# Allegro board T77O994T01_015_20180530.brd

Outline 210 x 96.2 mm; copper layers: TOP, G02, T03, G04, T05, P06, P07, T08, G09, T10, G11, BOTTOM. Coordinates in mm from the lower left corner of the outline.
Outline path: 0,95.2 0,12.7 arc(0.29,11.99) 1,11.7 14.7,11.7 14.7,3.2 15.2,2.7 25.4,2.7 25.9,3.2 25.9,10.3 arc(26.85,11.25) 27.8,10.3 27.8,3.2 28.3,2.7 98.5,2.7 99,3.2 99,10.75 arc(99.28,11.42) 99.95,11.7 121.55,11.7 arc(122.22,11.42) 122.5,10.75 122.5,0 209,0 arc(209.71,0.29) 210,1 210,95.2 arc(209.71,95.91) 209,96.2 1,96.2 arc(0.29,95.91) 0,95.2

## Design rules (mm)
net group BDX_CLKIN_SATA: nets BDX_CLKIN_SATA_N BDX_CLKIN_SATA_P
net group BUS-CPU_I2C2-1: nets LAN_MDC0_I2C_CLK_1V05 LAN_MDIO0_I2C_DATA_1V05
net group BUS-CPU_I2C2-2: nets LAN_MDC0_I2C_CLK_3V3 LAN_MDIO0_I2C_DATA_3V3
net group BUS-DDR4_TEST: nets PD_TEST0 PD_TEST1
net group BUS-DDR4_VREF: nets VP1P2_DDR4_AB_VREFCA VP1P2_DDR4_VREF
net group CLK_100M_PCIE0_SLOT: nets CLK_100M_PCIE0_SLOT_N CLK_100M_PCIE0_SLOT_P
net group CLK_100M_XDP_PE: nets CLK_100M_XDP_PE_N CLK_100M_XDP_PE_P
net group CPU_USB_P0: nets USB2_PCH_P0_DN USB2_PCH_P0_DP
net group DIFFPAIR0: nets USB2_PCH_P3_DN USB2_PCH_P3_DP
net group DIFFPAIR1: nets USB2_P2_DN USB2_P2_DP
net group G2_PCIE_RX0: nets G2_PCIE_RX0_N G2_PCIE_RX0_P
net group G2_PCIE_RX1: nets G2_PCIE_RX1_N G2_PCIE_RX1_P
net group G2_PCIE_TX0_AC_N: nets G2_PCIE_TX0_AC_N G2_PCIE_TX0_N
net group G2_PCIE_TX0_AC_P: nets G2_PCIE_TX0_AC_P G2_PCIE_TX0_P
net group G2_PCIE_TX1_AC_N: nets G2_PCIE_TX1_AC_N G2_PCIE_TX1_N
net group G2_PCIE_TX1_AC_P: nets G2_PCIE_TX1_AC_P G2_PCIE_TX1_P
net group G3_PCIE_RX0: nets G3_PCIE_RX0_N G3_PCIE_RX0_P
net group G3_PCIE_RX1: nets G3_PCIE_RX1_N G3_PCIE_RX1_P
net group G3_PCIE_RX2: nets G3_PCIE_RX2_N G3_PCIE_RX2_P
net group G3_PCIE_RX3: nets G3_PCIE_RX3_N G3_PCIE_RX3_P
net group G3_PCIE_TX0_AC_N: nets G3_PCIE_TX0_AC_N G3_PCIE_TX0_N
net group G3_PCIE_TX0_AC_P: nets G3_PCIE_TX0_AC_P G3_PCIE_TX0_P
net group G3_PCIE_TX1_AC_N: nets G3_PCIE_TX1_AC_N G3_PCIE_TX1_N
net group G3_PCIE_TX1_AC_P: nets G3_PCIE_TX1_AC_P G3_PCIE_TX1_P
net group G3_PCIE_TX2_AC_N: nets G3_PCIE_TX2_AC_N G3_PCIE_TX2_N
net group G3_PCIE_TX2_AC_P: nets G3_PCIE_TX2_AC_P G3_PCIE_TX2_P
net group G3_PCIE_TX3_AC_N: nets G3_PCIE_TX3_AC_N G3_PCIE_TX3_N
net group G3_PCIE_TX3_AC_P: nets G3_PCIE_TX3_AC_P G3_PCIE_TX3_P
net group P_CPU_CCS1: nets P_CPU_CCSN1_10 P_CPU_CCSP1_10
net group P_DDR4_VS: nets P_DDR4_CGFB_10 P_DDR4_CVFB_10
net group PD_CLKIN_CPY: nets PD_CLKIN_CPY_N PD_CLKIN_CPY_P
net group PD_CLKIN_DMI: nets PD_CLKIN_DMI_N PD_CLKIN_DMI_P
net group PD_CLKIN_DOT96: nets PD_CLKIN_DOT96_N PD_CLKIN_DOT96_P
net group PD_CPU_TSTCLK: nets PD_CPU_TSTCLK_N PD_CPU_TSTCLK_P
net group SATA3_SSD_RX_N: nets SATA3_SSD_RX_N SATA_P2_RX_N
net group SATA3_SSD_RX_P: nets SATA3_SSD_RX_P SATA_P2_RX_P
net group SATA3_SSD_TX_N: nets SATA3_SSD_TX_N SATA_P2_TX_AC_N
net group SATA3_SSD_TX_P: nets SATA3_SSD_TX_P SATA_P2_TX_AC_P
net group SFPP0_KR_RX0_AC_N: nets SFPP0_KR_RX0_AC_N SFPP0_KR_RX0_N
net group SFPP0_KR_RX0_AC_P: nets SFPP0_KR_RX0_AC_P SFPP0_KR_RX0_P
net group SFPP0_KR_TX0: nets SFPP0_KR_TX0_N SFPP0_KR_TX0_P
net group SFPP1_KR_RX1_AC_N: nets SFPP1_KR_RX1_AC_N SFPP1_KR_RX1_N
net group SFPP1_KR_RX1_AC_P: nets SFPP1_KR_RX1_AC_P SFPP1_KR_RX1_P
net group SFPP1_KR_TX1: nets SFPP1_KR_TX1_N SFPP1_KR_TX1_P
net group USB2_PCH_P1_D: nets USB2_PCH_P1_DN USB2_PCH_P1_DP
net group USB2_PCH_P2_D: nets USB2_PCH_P2_DN USB2_PCH_P2_DP
net group VP1P05_SNS: nets VP1P05_GSNS VP1P05_VSNS
net group BUS-DDR4_A-ADDR/COMM: nets DDR4_A_A0 DDR4_A_A1 DDR4_A_A2 DDR4_A_A3 DDR4_A_A4 DDR4_A_A5 DDR4_A_A6 DDR4_A_A7 DDR4_A_A8 DDR4_A_A9 DDR4_A_A10 DDR4_A_A11 DDR4_A_A12 DDR4_A_A13 DDR4_A_A14 DDR4_A_A15 DDR4_A_A16 DDR4_A_ACT_L DDR4_A_BA0 DDR4_A_BA1 DDR4_A_BG0 DDR4_A_BG1 DDR4_A_PAR
net group BUS-DDR4_A-ALERT: nets DDR4_A_ALERT_L
net group BUS-DDR4_A-CONTROL: nets DDR4_A_CKE0 DDR4_A_CKE1 DDR4_A_CS0_L DDR4_A_CS1_L DDR4_A_ODT0 DDR4_A_ODT1
net group BUS-DDR4_A-DATA_0: nets DDR4_A_DQ0 DDR4_A_DQ1 DDR4_A_DQ2 DDR4_A_DQ3 DDR4_A_DQ4 DDR4_A_DQ5 DDR4_A_DQ6 DDR4_A_DQ7 DDR4_A_DQS0_N DDR4_A_DQS0_P
net group BUS-DDR4_A-DATA_1: nets DDR4_A_DQ8 DDR4_A_DQ9 DDR4_A_DQ10 DDR4_A_DQ11 DDR4_A_DQ12 DDR4_A_DQ13 DDR4_A_DQ14 DDR4_A_DQ15 DDR4_A_DQS1_N DDR4_A_DQS1_P
net group BUS-DDR4_A-DATA_2: nets DDR4_A_DQ16 DDR4_A_DQ17 DDR4_A_DQ18 DDR4_A_DQ19 DDR4_A_DQ20 DDR4_A_DQ21 DDR4_A_DQ22 DDR4_A_DQ23 DDR4_A_DQS2_N DDR4_A_DQS2_P
net group BUS-DDR4_A-DATA_3: nets DDR4_A_DQ24 DDR4_A_DQ25 DDR4_A_DQ26 DDR4_A_DQ27 DDR4_A_DQ28 DDR4_A_DQ29 DDR4_A_DQ30 DDR4_A_DQ31 DDR4_A_DQS3_N DDR4_A_DQS3_P
net group BUS-DDR4_A-DATA_4: nets DDR4_A_DQ32 DDR4_A_DQ33 DDR4_A_DQ34 DDR4_A_DQ35 DDR4_A_DQ36 DDR4_A_DQ37 DDR4_A_DQ38 DDR4_A_DQ39 DDR4_A_DQS4_N DDR4_A_DQS4_P
net group BUS-DDR4_A-DATA_5: nets DDR4_A_DQ40 DDR4_A_DQ41 DDR4_A_DQ42 DDR4_A_DQ43 DDR4_A_DQ44 DDR4_A_DQ45 DDR4_A_DQ46 DDR4_A_DQ47 DDR4_A_DQS5_N DDR4_A_DQS5_P
net group BUS-DDR4_A-DATA_6: nets DDR4_A_DQ48 DDR4_A_DQ49 DDR4_A_DQ50 DDR4_A_DQ51 DDR4_A_DQ52 DDR4_A_DQ53 DDR4_A_DQ54 DDR4_A_DQ55 DDR4_A_DQS6_N DDR4_A_DQS6_P
net group BUS-DDR4_A-DATA_7: nets DDR4_A_DQ56 DDR4_A_DQ57 DDR4_A_DQ58 DDR4_A_DQ59 DDR4_A_DQ60 DDR4_A_DQ61 DDR4_A_DQ62 DDR4_A_DQ63 DDR4_A_DQS7_N DDR4_A_DQS7_P
net group BUS-DDR4_A-DATA_8: nets DDR4_A_DQS8_N DDR4_A_DQS8_P DDR4_A_ECC0 DDR4_A_ECC1 DDR4_A_ECC2 DDR4_A_ECC3 DDR4_A_ECC4 DDR4_A_ECC5 DDR4_A_ECC6 DDR4_A_ECC7
net group BUS-DDR4_A_CLK: nets CLK_DDR4_A_CK0_N CLK_DDR4_A_CK0_P CLK_DDR4_A_CK2_N CLK_DDR4_A_CK2_P
net group BUS-DDR4_A_OTHER: nets DDR4_A_SA0 DDR4_A_SA1 DDR4_A_SA2
net group BUS-DDR4_B-ADDR/COMM: nets DDR4_B_A0 DDR4_B_A1 DDR4_B_A2 DDR4_B_A3 DDR4_B_A4 DDR4_B_A5 DDR4_B_A6 DDR4_B_A7 DDR4_B_A8 DDR4_B_A9 DDR4_B_A10 DDR4_B_A11 DDR4_B_A12 DDR4_B_A13 DDR4_B_A14 DDR4_B_A15 DDR4_B_A16 DDR4_B_ACT_L DDR4_B_BA0 DDR4_B_BA1 DDR4_B_BG0 DDR4_B_BG1 DDR4_B_PAR
net group BUS-DDR4_B-ALERT: nets DDR4_B_ALERT_L
net group BUS-DDR4_B-CONTROL: nets DDR4_B_CKE0 DDR4_B_CKE1 DDR4_B_CS0_L DDR4_B_CS1_L DDR4_B_ODT0 DDR4_B_ODT1
net group BUS-DDR4_B-DATA_0: nets DDR4_B_DQ0 DDR4_B_DQ1 DDR4_B_DQ2 DDR4_B_DQ3 DDR4_B_DQ4 DDR4_B_DQ5 DDR4_B_DQ6 DDR4_B_DQ7 DDR4_B_DQS0_N DDR4_B_DQS0_P
net group BUS-DDR4_B-DATA_1: nets DDR4_B_DQ8 DDR4_B_DQ9 DDR4_B_DQ10 DDR4_B_DQ11 DDR4_B_DQ12 DDR4_B_DQ13 DDR4_B_DQ14 DDR4_B_DQ15 DDR4_B_DQS1_N DDR4_B_DQS1_P
net group BUS-DDR4_B-DATA_2: nets DDR4_B_DQ16 DDR4_B_DQ17 DDR4_B_DQ18 DDR4_B_DQ19 DDR4_B_DQ20 DDR4_B_DQ21 DDR4_B_DQ22 DDR4_B_DQ23 DDR4_B_DQS2_N DDR4_B_DQS2_P
net group BUS-DDR4_B-DATA_3: nets DDR4_B_DQ24 DDR4_B_DQ25 DDR4_B_DQ26 DDR4_B_DQ27 DDR4_B_DQ28 DDR4_B_DQ29 DDR4_B_DQ30 DDR4_B_DQ31 DDR4_B_DQS3_N DDR4_B_DQS3_P
net group BUS-DDR4_B-DATA_4: nets DDR4_B_DQ32 DDR4_B_DQ33 DDR4_B_DQ34 DDR4_B_DQ35 DDR4_B_DQ36 DDR4_B_DQ37 DDR4_B_DQ38 DDR4_B_DQ39 DDR4_B_DQS4_N DDR4_B_DQS4_P
net group BUS-DDR4_B-DATA_5: nets DDR4_B_DQ40 DDR4_B_DQ41 DDR4_B_DQ42 DDR4_B_DQ43 DDR4_B_DQ44 DDR4_B_DQ45 DDR4_B_DQ46 DDR4_B_DQ47 DDR4_B_DQS5_N DDR4_B_DQS5_P
net group BUS-DDR4_B-DATA_6: nets DDR4_B_DQ48 DDR4_B_DQ49 DDR4_B_DQ50 DDR4_B_DQ51 DDR4_B_DQ52 DDR4_B_DQ53 DDR4_B_DQ54 DDR4_B_DQ55 DDR4_B_DQS6_N DDR4_B_DQS6_P
net group BUS-DDR4_B-DATA_7: nets DDR4_B_DQ56 DDR4_B_DQ57 DDR4_B_DQ58 DDR4_B_DQ59 DDR4_B_DQ60 DDR4_B_DQ61 DDR4_B_DQ62 DDR4_B_DQ63 DDR4_B_DQS7_N DDR4_B_DQS7_P
net group BUS-DDR4_B-DATA_8: nets DDR4_B_DQS8_N DDR4_B_DQS8_P DDR4_B_ECC0 DDR4_B_ECC1 DDR4_B_ECC2 DDR4_B_ECC3 DDR4_B_ECC4 DDR4_B_ECC5 DDR4_B_ECC6 DDR4_B_ECC7
net group BUS-DDR4_B_CLK: nets CLK_DDR4_B_CK0_N CLK_DDR4_B_CK0_P CLK_DDR4_B_CK2_N CLK_DDR4_B_CK2_P
net group BUS-DDR4_B_OTHER: nets DDR4_B_SA0 DDR4_B_SA1 DDR4_B_SA2
net group BUS-DDR4_RCOMP: nets DDR_RCOMP0 DDR_RCOMP1 DDR_RCOMP2
net group BUS-SPI-1: nets SPI_SSB_CS0_L
net group BUS-UART: nets CPU_UART0_TXD_1V05 CPU_UART0_TXD_3V3 CPU_UART1_TXD_1V05 CPU_UART1_TXD_3V3
net group BUS_LED: nets LED_CPLD_1 LED_CPLD_1_R LED_CPLD_2 LED_CPLD_2_R LED_CPLD_3 LED_CPLD_3_R LED_CPLD_4 LED_CPLD_4_R
net group CLK: nets CLK_25M_CPLD CLK_25M_CPLD_ST CLK_33M_BUF CLK_33M_BUF_ST CLK_33M_LPC CLK_33M_LPC_EDGE CLK_33M_LPC_EDGE_ST CLK_33M_LPC_HDR CLK_33M_LPC_HDR_ST CLK_33M_LPC_ST CLK_M2_SUSCLK CLK_M2_SUSCLK_ST
net group POWER: nets N50983122 N50983135 P_CPU_CCSN1+_10 P_CPU_CCSN2+_10 P_CPU_CCSP1+_10 P_CPU_CCSP2+_10 P_CPU_SKIP#_1_10 P_CPU_SKIP#_2_10 P_CPU_SKIP#_10 PWRGD_VP1P05_PCH PWRGD_VP2P5_DDR4_VPP VFLTP1P05_PCH VP0P6_DDR4_VTT_REFOUT VP1P3_FB VP1P3_SS VP1P5__PCH_FB VP1P05_BLEED VP1P05_PCH_SLEWRATE VP1P5_PCH_SS VP1P7_COMP VP1P7_COMP_RC VP1P7_FB VP1P7_RT VP1P7_SNS VP1P7_SS VP2P5 VP2P5_DDR4_VPP_FB VP2P5_DDR4_VPP_FB_IN VP2P5_DDR4_VPP_L_RC VP2P5_DDR4_VPP_SN VP2P5_DDR4_VPP_SS VP3P3_A_BLEED VP3P3_BAT VP3P3_BAT_SOURCE VP3P3_SF100 VP3P3_SPI VP3P3_VFB VP3P3_VREG5 VP3P3_VSENSE VP5P0_FB VP5P0_FB_IN VP5P0_L_RC VP5P0_SN VP5P0_SS
net group POWER_20MIL: nets P_CPU_CPWM1_10 P_CPU_CPWM1_DR1_10 P_CPU_CPWM2_10 P_CPU_CPWM2_DR2_10 P_CPU_DR1_BST_20 P_CPU_DR1_BST_RC_20 P_CPU_DR1_BSTR_20 P_CPU_DR2_BST_20 P_CPU_DR2_BST_RC_20 P_CPU_DR2_BSTR_20 P_CPU_SB1_20 P_CPU_SB2_20 P_DDR4_CPWM1_DR1_10 P_DDR4_DR1_BST_20 P_DDR4_DR1_BST_RC_20 P_DDR4_DR1_BSTR_20 P_DDR4_PWM1 P_DDR4_SB1_20 VP1P7_BOOT VP2P5_DDR4_VPP_BST VP2P5_DDR4_VPP_BST_RC VP3P3_BST VP3P3_BSTR VP3P3_SNUBBER VP5P0_BST VP5P0_BST_RC
net group SMB_I2C: nets DDR4_SCL_2V5 DDR4_SCL_2V5_ST DDR4_SDA_1V05 DDR4_SDA_1V05_ST LAN_I2C0_SCL_1V05_R LAN_I2C0_SDA_1V05_R LAN_I2C1_SCL_1V05_R LAN_I2C1_SDA_1V05_R SMB_SMLINK0_3V3SB_CLK SMB_SMLINK0_3V3SB_DAT SMB_SMLINK1_3V3SB_CLK SMB_SMLINK1_3V3SB_DAT
net group SPI: nets SPI_BUF_SSB_CLK SPI_BUF_SSB_CS0_L SPI_BUF_SSB_CS1_L SPI_BUF_SSB_MISO_ST SPI_BUF_SSB_MOSI SPI_MUX_SSB_CS0_L SPI_SSB_CLK SPI_SSB_CLK_ST
net group SVID: nets BDXDE_SVID_ALERT_L P_CPU_ALERT P_CPU_VCLK P_CPU_VDIO P_DDR4_ALERT P_DDR4_VCLK P_DDR4_VDIO SVID_CPU_ALERT_L SVID_CPU_DIO VP1P05_ALERT
net group UART: nets CPU_UART0_RXD_1V05 CPU_UART0_RXD_3V3 CPU_UART1_RXD_1V05 CPU_UART1_RXD_3V3
net group XTAL: nets BDXDE_RTCX1 BDXDE_RTCX2 KR_EPHY_REFCLK_IN KR_EPHY_REFCLK_OUT XTAL_PCH_25M_IN XTAL_PCH_25M_OUT

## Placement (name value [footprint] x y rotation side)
BAT1  BB3320E-1  [BA-D23_1X5_8-3S0]  204.45 42.53 90 top
C1  220nF  [C-0402S0]  49.38 12.59 180 top
C2  220nF  [C-0402S0]  53.26 12.72 180 top
C3  220nF  [C-0402S0]  57.38 12.46 180 top
C4  220nF  [C-0402S0]  61.44 12.46 180 top
C5  220nF  [C-0402S0]  50.52 12.59 180 top
C6  220nF  [C-0402S0]  54.33 12.72 180 top
C7  220nF  [C-0402S0]  58.4 12.49 180 top
C8  220nF  [C-0402S0]  62.46 12.46 180 top
C9  100nF  [C-0402S0]  78.38 12.51 180 top
C10  100nF  [C-0402S0]  74.4 12.31 180 top
C11  100nF  [C-0402S0]  79.4 12.51 180 top
C12  100nF  [C-0402S0]  75.41 12.31 180 top
C13  100nF  [C-0402S0]  103.86 52.98 270 top
C14  100nF  [C-0402S0]  103.94 48.53 270 top
C15  100nF  [C-0402S0]  103.86 52.03 270 top
C16  100nF  [C-0402S0]  103.94 49.47 270 top
C17  27pF  [C-0402S0]  104.42 55.24 180 top
C18  27pF  [C-0402S0]  104.42 57.14 0 top
C19  100nF  [C-0402S0]  82.57 66.56 90 top
C20  100nF  [C-0402S0]  84.6 66.56 90 top
C21  100nF  [C-0402S0]  72.23 70.14 270 bottom
C22  100nF  [C-0402S0]  42.82 63.1 270 bottom
C23  100nF  [C-0402S0]  83.9 25.18 0 bottom
C24  100nF  [C-0402S0]  72.23 70.14 90 top
C25  100nF  [C-0402S0]  80.1 67.42 180 top
C26  18pF  [C-0402S0]  121.79 21.22 90 top
C27  18pF  [C-0402S0]  124.08 21.22 270 top
C28  100nF  [C-0402S0]  46.23 19.96 180 bottom
C29  100nF  [C-0402S0]  87.1 71.52 90 top
C30  100nF  [C-0402S0]  140.22 90.57 0 top
C31  1uF  [C-0402S0]  123.08 52.83 180 bottom
C32  1uF  [C-0402S0]  181.32 89.82 180 top
C33  1uF  [C-0402S0]  198.63 13.1 0 top
C34  22uF  [C-1210B-H2_8]  90.04 20.84 0 bottom
C35  1uF  [C-0402S0]  197.61 3.95 0 bottom
C36  10pF  [C-0402S0]  111.65 23.62 90 top
C37  10pF  [C-0402S0]  113.31 23.62 270 top
C38  100nF  [C-0402B-U58O293T00]  126.45 35.07 90 bottom
C39  47uF  [C-0805-H1_35]  99.97 45.1 0 top
C40  1uF  [C-0402B-U58O293T00]  116.51 47.19 0 bottom
C41  100nF  [C-0402B-U58O293T00]  123.8 43.17 180 bottom
C42  100nF  [C-0402B-U58O293T00]  123.83 34.57 90 bottom
C43  100nF  [C-0402B-U58O293T00]  123.83 33.75 90 bottom
C44  100nF  [C-0402S0]  36.31 56.53 90 top
C45  1uF  [C-0402B-U58O293T00]  125.03 36.57 180 bottom
C46  1uF  [C-0402B-U58O293T00]  119.93 41.88 90 bottom
C47  1uF  [C-0402B-U58O293T00]  119.22 32.97 0 bottom
C48  1uF  [C-0402B-U58O293T00]  118.81 34.18 90 bottom
C49  1uF  [C-0402B-U58O293T00]  119.03 35.37 270 bottom
C50  1uF  [C-0402B-U58O293T00]  119.03 36.17 90 bottom
C51  100nF  [C-0402S0]  51.91 82.96 180 bottom
C52  100nF  [C-0402B-U58O293T00]  120.63 36.17 90 bottom
C53  10nF  [C-0402S0]  126.31 38.66 0 bottom
C54  1uF  [C-0402S0]  83.34 27.55 90 top
C55  1uF  [C-0402S0]  119.4 51.53 0 bottom
C56  47uF  [C-0603S0]  118.28 49.93 90 bottom
C57  1uF  [C-0402B-U58O293T00]  121.81 36.54 180 bottom
C58  1uF  [C-0402B-U58O293T00]  122.23 37.77 90 bottom
C59  1uF  [C-0402B-U58O293T00]  123.77 39.62 315 bottom
C60  1uF  [C-0402B-U58O293T00]  121.43 39.37 270 bottom
C61  1uF  [C-0402B-U58O293T00]  122.23 38.57 270 bottom
C62  1uF  [C-0402B-U58O293T00]  119.04 37.77 270 bottom
C63  1uF  [C-0402B-U58O293T00]  118.23 38.57 270 bottom
C64  100nF  [C-0402B-U58O293T00]  122.63 36.57 180 bottom
C65  10uF  [C-0603S0]  94.38 31.62 0 bottom
C66  22uF  [C-0603S0]  122.96 46.48 270 bottom
C67  22uF  [C-0603S0]  122.98 47.85 270 bottom
C68  22uF  [C-0603S0]  126.89 46.27 270 bottom
C69  22uF  [C-0603S0]  126.89 47.7 270 bottom
C70  22uF  [C-0603S0]  122.96 49.22 270 bottom
C71  22uF  [C-0603S0]  123 50.59 270 bottom
C72  22uF  [C-0603S0]  123.01 45.11 270 bottom
C73  22uF  [C-0603S0]  126.87 51.96 270 bottom
C74  22uF  [C-0603S0]  129.97 53.23 90 bottom
C75  1uF  [C-0402B-U58O293T00]  118.23 39.37 270 bottom
C76  1uF  [C-0402B-U58O293T00]  120.23 37.37 0 bottom
C77  1uF  [C-0402B-U58O293T00]  121.44 40.17 270 bottom
C78  1uF  [C-0402B-U58O293T00]  119.99 40.02 180 bottom
C79  1uF  [C-0402B-U58O293T00]  122.63 40.57 180 bottom
C80  1uF  [C-0402B-U58O293T00]  124.43 41.67 180 bottom
C81  1uF  [C-0402B-U58O293T00]  121.26 41.12 270 bottom
C82  22uF  [C-0603S0]  129.94 47.75 90 bottom
C83  22uF  [C-0603S0]  129.94 46.38 90 bottom
C84  22uF  [C-0603S0]  129.97 51.86 90 bottom
C85  22uF  [C-0603S0]  129.97 50.49 90 bottom
C86  22uF  [C-0603S0]  129.94 49.12 90 bottom
C87  22uF  [C-0603S0]  126.89 49.09 270 bottom
C88  22uF  [C-0603S0]  126.89 50.49 270 bottom
C89  47uF  [C-0603S0]  118.28 47.19 90 bottom
C90  47uF  [C-0603S0]  118.28 48.56 90 bottom
C91  2.2uF  [C-0402S0]  117.75 42.64 90 bottom
C92  47uF  [C-0805-H1_35]  89.41 41.04 90 bottom
C93  47uF  [C-0603S0]  112.01 50.69 0 bottom
C94  47uF  [C-0603S0]  120.62 51 0 bottom
C95  47uF  [C-0603S0]  118.11 43.84 90 bottom
C96  47uF  [C-0603S0]  118.11 45.21 90 bottom
C97  100uF  [C-1210]  88.9 51.83 180.1 top
C98  47uF  [C-0805-H1_35]  89.41 36.72 90 bottom
C99  22uF  [C-0603S0]  132.28 45.46 270 bottom
C100  47uF  [C-0805-H1_35]  132.79 51.43 180 bottom
C101  47uF  [C-0805-H1_35]  132.79 48.13 0 bottom
C102  10uF  [C-0402A]  186.79 6.06 180 bottom
C103  1uF  [C-0402S0]  72.47 27.42 270 bottom
C104  22uF  [C-1210B-H2_8]  191.26 39.77 0 bottom
C107  100nF  [C-0402S0]  188.34 8.65 90 bottom
C108  100nF  [C-0402S0]  191.26 4.84 180 bottom
C114  47uF  [C-0805-H1_35]  102 38.35 270 top
C116  1uF  [C-0402S0]  32.35 44.61 90 top
C117  1uF  [C-0402S0]  38.19 65.06 90 bottom
C118  1uF  [C-0402S0]  31.73 41.29 270 top
C119  1uF  [C-0402S0]  27.24 69.1 90 top
C120  100nF  [C-0402S0]  93.55 25.18 90 bottom
C121  1uF  [C-0402S0]  27.41 65.29 270 bottom
C122  1uF  [C-0402S0]  26.65 31 180 top
C123  1uF  [C-0402S0]  82.77 26.45 0 bottom
C124  1uF  [C-0402S0]  47.37 29.1 180 top
C125  1uF  [C-0402S0]  68.55 28.61 180 top
C126  1uF  [C-0402S0]  46.61 24.53 180 top
C127  100nF  [C-0402S0]  139.55 81.17 180 top
C128  100nF  [C-0402S0]  120.56 34.58 180 bottom
C129  1uF  [C-0402S0]  36.93 31.77 180 top
C130  1uF  [C-0402S0]  38.24 69.74 270 top
C131  1uF  [C-0402S0]  72.92 31.61 180 top
C132  100nF  [C-0402S0]  199.01 10.68 90 bottom
C133  100nF  [C-0402S0]  182.05 3.93 180 bottom
C134  100nF  [C-0402S0]  187.83 12.34 90 bottom
C135  100nF  [C-0402S0]  155.54 3.84 180 top
C136  100nF  [C-0402S0]  167.35 4.4 90 bottom
C137  10nF  [C-0402S0]  155.42 65.55 270 top
C138  10uF  [C-0603S0]  189.89 83.45 90 bottom
C139  10uF  [C-0603S0]  162.15 79.36 180 top
C140  10uF  [C-0603S0]  178.59 91.05 270 top
C141  10uF  [C-0603S0]  174.2 89.7 270 bottom
C144  10nF  [C-0402S0]  175.18 61.13 180 bottom
C145  10uF  [C-0603S0]  160.76 79.36 180 top
C146  10uF  [C-0603S0]  189.89 82.06 90 bottom
C147  10uF  [C-0603S0]  178.59 89.62 270 top
C148  10uF  [C-0603S0]  178.51 89.7 90 bottom
C151  1uF  [C-0402B-U58O293T00]  116.63 52.83 90 bottom
C152  100nF  [C-0402S0]  84.17 19.46 0 top
C153  100nF  [C-0402S0]  123.71 37.03 180 bottom
C154  100nF  [C-0402S0]  167.39 10.05 270 bottom
C155  1uF  [C-0402S0]  53.48 60.89 90 bottom
C156  100nF  [C-0402S0]  200.41 12.97 0 bottom
C157  100nF  [C-0402S0]  72.42 26.02 90 top
C158  1uF  [C-0402S0]  67.23 41.46 180 top
C159  100uF  [C-1210]  61.21 28.21 180 top
C160  22uF  [C-0603S0]  62.71 47.13 270 top
C161  22uF  [C-0603S0]  37.06 35.45 90 top
C162  220nF  [C-0402S0]  50.13 37.63 0 bottom
C163  220nF  [C-0402S0]  47.39 39.23 0 bottom
C164  220nF  [C-0402S0]  42.65 53.1 0 top
C165  220nF  [C-0402S0]  37.19 36.72 90 top
C166  220nF  [C-0402S0]  48.26 44.59 180 bottom
C167  220nF  [C-0402S0]  46.96 43.16 90 bottom
C168  220nF  [C-0402S0]  51.15 37.12 0 bottom
C169  220nF  [C-0402S0]  52.32 41.29 270 bottom
C170  220nF  [C-0402S0]  50.29 43.83 0 bottom
C171  10pF  [C-0402S0]  61.95 37.73 270 top
C172  10pF  [C-0402S0]  37.31 47.39 90 top
C173  10pF  [C-0402S0]  42.8 55.01 270 top
C174  10pF  [C-0402S0]  45.94 32.29 90 bottom
C175  10pF  [C-0402S0]  61.95 38.75 270 top
C176  1uF  [C-0402B-U58O293T00]  121.83 34.17 0 bottom
C177  10nF  [C-0402S0]  114.58 29.08 270 bottom
C178  1uF  [C-0402S0]  114.58 30.09 270 bottom
C179  1uF  [C-0402B-U58O293T00]  124.58 38.17 0 bottom
C180  1uF  [C-0402B-U58O293T00]  125.03 34.97 0 bottom
C181  1uF  [C-0402B-U58O293T00]  122.96 43.19 180 bottom
C182  1uF  [C-0402S0]  135.28 29.84 90 bottom
C183  1uF  [C-0402B-U58O293T00]  128.21 37.8 225 bottom
C185  47uF  [C-0805-H1_35]  53.13 67.58 180 bottom
C186  100uF  [C-TAN-S7_3X4_3]  71.77 90.06 90 bottom
C187  100nF  [C-0402S0]  19.62 61.5 270 top
C188  100nF  [C-0402S0]  5.85 69.74 90 bottom
C189  100nF  [C-0402S0]  19.62 65.42 270 top
C190  47uF  [C-0805-H1_35]  11.4 73.19 180 bottom
C191  47uF  [C-0805-H1_35]  5.97 65.42 0 bottom
C192  100nF  [C-0402S0]  19.62 64.4 270 top
C193  100nF  [C-0402S0]  19.62 62.37 270 top
C198  100nF  [C-0402S0]  53.72 87.39 90 top
C199  10nF  [C-0402S0]  151.51 59.45 90 top
C200  100nF  [C-0402S0]  70.74 72.91 270 top
C201  10nF  [C-0402S0]  69.52 74.36 90 bottom
C202  10nF  [C-0402S0]  69.52 75.38 90 bottom
C203  10nF  [C-0402S0]  69.52 76.39 90 bottom
C204  10nF  [C-0402S0]  69.52 77.41 90 bottom
C205  100nF  [C-0402S0]  92.3 72.25 0 top
C206  100nF  [C-0402S0]  52.8 82.96 180 bottom
C207  1uF  [C-0402S0]  53.69 82.96 180 bottom
C208  22uF  [C-0805]  38.15 77.54 180 top
C209  1uF  [C-0402S0]  70.5 37.61 180 top
C210  1uF  [C-0402S0]  62.23 43.32 90 top
C3812  1uF  [C-0402B-U58O293T00]  119.03 36.97 90 bottom
C3813  1uF  [C-0402B-U58O293T00]  114.83 37.71 90 bottom
CN1  ASAA821-EARB0-7H  [CN-EXPPCI-260C]  182.2 50.54 90 bottom
CN2  AS0A826-H2RB-7H  [CN-EXPPCI-260A-T77O759]  170.46 50.59 90 top
D1  LTST-C190KGKT  [LD-0603S0]  146.02 13.11 0 top
D2  BAT54C-7-F  [SOT-23BH1_11]  194.89 40.55 270 bottom
D3  LTST-C190KGKT  [LD-0603S0-H0_55]  58.9 56.28 0 top
D4  LTST-C190KGKT  [LD-0603S0-H0_55]  57.51 56.28 0 top
D5  LTST-C190KGKT  [LD-0603S0-H0_55]  55.6 56.28 0 top
D6  LTST-C190KGKT  [LD-0603S0-H0_55]  54.2 56.28 0 top
D7  BAT54C-7-F  [SOT-23BH1_11]  164.05 11.21 90 top
D8  BAT54C-7-F  [SOT-23BH1_11]  83.82 21.99 180 bottom
H1  11802936A  [NUT165R276-H5_7]  19.63 74.44 180 bottom
J1  HS5507F-R  [CN-S7X2-2HDS1]  43.56 19.7 270 top
J2  20438-04021  [CN-S10_16X5_1-4]  147.32 5.99 90 top
J3  20438-04021  [CN-S10_16X5_1-4]  201.29 6.62 90 top
J6  HS1104V-RN  [CN-S4X2-2_54HD]  175.28 6.87 270 top
J8  HS1105H-RN  [CN-S5X2-2_54AHDS0]  26.26 19.95 270 top
J9  AS0BC23-S67BM-LH  [CN-EXPPCI-75G]  61.28 74.44 180 bottom
J10  10061913-113  [CN-EXPPCI-164FPCS0]  56.85 9.07 90 bottom
J11  26-01-3115  [CN-D2X2-4_2RT]  9.5 32.53 90 top
J12  QT510301-22-7F  [CN-S30X2-0_5ASK]  8.69 69.61 180 top
L1  0.02ohm  [R-1210]  95.44 34.79 0 top
L2  8.2nH  [L-U58O293T00]  96.67 42.03 0 top
L3  8.2nH  [L-U58O293T00]  96.67 38.88 0 top
L7  8.2nH  [L-U58O293T00]  104.92 34.81 180 bottom
M1  Hole-3.4mm  [GMTH134R394KO472]  5 88.2 0 top
M2  Hole-3.4mm  [GMTH134R394KO472]  205 19.7 0 top
M3  Hole-3.4mm  [GMTH134R394KO472]  5 19.69 0 top
M4  Hole-3.4mm  [GMTH134R394KO472]  205 88.2 0 top
MHS1  SMT NUT PAD  [ICT295PAS0]  101.08 21.2 0 top
MHS2  Screw  [MPTH126R295]  101.08 71.2 0 top
MHS3  SMT NUT PAD  [ICT295PAS0]  151.08 71.2 0 top
MHS4  Screw  [MPTH126R295]  151.08 21.2 0 top
NOREF  -  [unnamed]  194.84 17.13 0 top
NOREF#2  -  [unnamed]  15.59 89.34 0 top
NOREF#3  -  [unnamed]  194.23 86.16 0 top
NOREF#4  -  [unnamed]  15.59 89.34 180 bottom
NOREF#5  -  [unnamed]  194.84 17.13 180 bottom
NOREF#6  -  [unnamed]  194.23 86.16 180 bottom
PC1  22uF  [C-1210]  4 53 0 top
PC2  100nF  [C-0603S0]  30.81 91.6 180 top
PC3  100nF  [C-0603S0]  8.95 53 0 top
PC4  100nF  [C-0603S0]  13.7 44.66 0 top
PC5  100nF  [C-0402S0]  15.71 49.79 270 bottom
PC6  100nF  [C-0603S0]  16 52.85 180 bottom
PC7  1uF  [C-0603S0]  17.4 52.85 180 bottom
PC8  22uF  [C-1210]  20.45 52.34 180 bottom
PC9  22uF  [C-1210]  24.26 52.34 180 bottom
PC10  22uF  [C-1210]  21.21 52.21 0 top
PC11  8.2nF  [C-0402S0]  7.83 42.71 270 top
PC12  680pF  [C-0603S0]  10.88 53.26 180 bottom
PC13  1uF  [C-0603S0]  7.57 48.04 90 bottom
PC14  1nF  [C-0402S0]  14.3 48.3 0 bottom
PC15  100nF  [C-0402S0]  44.96 85.61 180 top
PC16  22uF  [C-1210]  42.29 85.87 180 top
PC17  22uF  [C-1210]  38.61 85.87 180 top
PC18  10pF  [C-0402S0]  47.19 79.06 0 top
PC19  100nF  [C-0402S0]  47.07 90.84 270 top
PC20  1uF  [C-0402S0]  49.27 79.06 180 top
PC21  1nF  [C-0402S0]  51.13 90.71 180 bottom
PC22  22uF  [C-1210]  53.85 80.79 90 top
PC23  22uF  [C-1210]  53.85 84.6 90 top
PC24  22uF  [C-0805]  31.62 77.49 90 top
PC25  100nF  [C-0402S0]  47.58 69.25 90 top
PC26  22uF  [C-0805]  48.13 70.88 90 top
PC27  1uF  [C-0402S0]  42.34 65.6 90 top
PC28  100nF  [C-0402S0]  31.62 75.84 90 top
PC29  10nF  [C-0402S0]  42.34 64.63 90 top
PC30  560pF  [C-0402S0]  49.76 64.28 180 top
PC31  22uF  [C-0805]  31.62 81.55 90 top
PC32  100nF  [C-0402S0]  57.53 71.77 0 top
PC33  22uF  [C-0805]  59.05 71.77 0 top
PC34  1uF  [C-0402S0]  52.82 76.82 0 top
PC35  100nF  [C-0402S0]  57.53 74.82 180 top
PC36  10nF  [C-0402S0]  51.86 76.82 0 top
PC37  560pF  [C-0402S0]  52.39 69.53 90 top
PC38  22uF  [C-0805]  130.05 85.11 180 bottom
PC39  22uF  [C-0805]  127.89 85.11 180 bottom
PC40  22uF  [C-0805]  125.73 85.11 180 bottom
PC41  22uF  [C-0805]  125.73 88.66 0 bottom
PC44  22uF  [C-0805]  130.05 92.22 180 bottom
PC45  22uF  [C-0805]  127.89 92.22 180 bottom
PC46  22uF  [C-0805]  125.73 92.22 180 bottom
PC47  22uF  [C-0805]  130.05 88.66 0 bottom
PC48  22uF  [C-0805]  127.89 88.66 0 bottom
PC52  22uF  [C-0805]  61.21 71.77 0 top
PC67  22pF  [C-0402S0]  27.38 83.47 180 top
PC68  100nF  [C-0402S0]  24.65 87.42 180 top
PC69  22uF  [C-1210]  21.72 86.76 180 top
PC70  22uF  [C-0805]  59.05 75.33 180 top
PC71  100nF  [C-0402S0]  45.04 69.25 270 top
PC72  22uF  [C-0805]  44.58 70.88 270 top
PC75  22uF  [C-0805]  197.36 49.42 180.2 top
PC77  1uF  [C-0402S0]  192.38 89.62 0 top
PC78  22uF  [C-0805]  186.56 90.95 0 bottom
PC79  22uF  [C-0805]  189.87 92.6 180 top
PC80  1uF  [C-0402S0]  191.52 9.41 90 bottom
PC81  1nF  [C-0402S0]  185.39 88.93 90 top
PC82  100nF  [C-0402S0]  180.82 93.23 90 top
PC83  1uF  [C-0402S0]  188.21 91.08 0 bottom
PC84  22uF  [C-0805]  192.33 92.55 180 top
PC111  22uF  [C-0805]  31.62 79.52 90 top
PC112  10pF  [C-0402S0]  28.07 91.31 0 top
PC113  100pF  [C-0402S0]  24.72 83.47 0 top
PC114  3.3nF  [C-0402S0]  30.05 83.47 180 top
PC115  22nF  [C-0402S0]  28.83 82.06 270 top
PC137  100nF  [C-0603S0]  155.02 83.43 90 top
PC139  100nF  [C-0603S0]  150.74 90.29 0 top
PC140  680pF  [C-0603S0]  152.67 90.55 180 bottom
PC142  10uF  [C-1206]  74.3 48.53 0 top
PC144  22uF  [C-1210B-H2_8]  75.82 47.77 180 bottom
PC146  22uF  [C-0805]  89.41 38.88 90.1 bottom
PC147  22uF  [C-0805]  89.96 51.98 0 bottom
PC148  22uF  [C-0805]  84.45 36.34 90 top
PC151  100nF  [C-0603S0]  74.12 38.55 180 top
PC152  470uF  [C-S7_3X4_3-2]  93.98 62.25 359.8 top
PC162  1uF  [C-0603S0]  200.3 32.66 90 bottom
PC163  100nF  [C-0603S0]  89.26 45.35 0 top
PC165  100nF  [C-0402S0]  95.14 87.77 270 top
PC166  2.2uF  [C-0603S0]  200.36 67.35 270 top
PC167  1nF  [C-0402S0]  108.6 88.86 270 bottom
PC168  10nF  [C-0402S0]  81.15 79.65 270 top
PC170  22uF  [C-1210B-H2_8]  91.57 82.31 180 top
PC171  100nF  [C-0402S0]  94.5 92.85 0 top
PC172  22uF  [C-1210B-H2_8]  87.88 82.31 180 top
PC173  470uF  [C-S7_3X4_3-2]  127.1 81.04 270 top
PC174  100uF  [C-TAN-S7_3X4_3]  15.26 20.72 0 top
PC175  1nF  [C-0402S0]  95.14 85.99 90 top
PC176  2.2uF  [C-0603S0]  104.79 88.15 180 top
PC177  1nF  [C-0402S0]  108.47 79.64 90 bottom
PC178  10nF  [C-0402S0]  79.63 80.28 90 top
PC179  470uF  [C-S7_3X4_3-2]  127.1 91.46 270 top
PC180  1nF  [C-0402S0]  95.14 76.09 90 top
PC182  22uF  [C-1210B-H2_8]  87.63 91.58 0 top
PC183  100nF  [C-0402S0]  94.5 80.79 180 top
PC184  22uF  [C-1210B-H2_8]  91.19 91.58 0 top
PC185  470uF  [C-S7_3X4_3-2]  127.1 86.25 270 top
PC186  100nF  [C-0402S0]  95.14 77.87 270 top
PC187  1uF  [C-0402S0]  76.94 70.63 180 top
PC188  1uF  [C-0402S0]  74.11 74.77 90 top
PC189  470nF  [C-0402S0]  74.1 77.31 90 top
PC190  220pF  [C-0402S0]  73.64 79.64 180 top
PC191  10pF  [C-0402S0]  74.52 79.64 180 top
PC192  1nF  [C-0402S0]  83.8 76.47 0 top
PC193  4.7nF  [C-0402S0]  85.08 75.15 270 top
PC194  22uF  [C-0805]  124.59 77.99 180 bottom
PC195  22uF  [C-0805]  123.57 81.55 0 bottom
PC196  22uF  [C-0805]  123.57 92.22 180 bottom
PC199  22uF  [C-0805]  119.13 92.22 180 bottom
PC200  22uF  [C-0805]  121.28 92.22 180 bottom
PC201  22uF  [C-0805]  125.73 81.55 0 bottom
PC202  22uF  [C-0805]  128.52 75.2 270 top
PC203  22uF  [C-0805]  123.57 85.11 180 bottom
PC204  22uF  [C-0805]  123.57 88.66 0 bottom
PC205  22uF  [C-0805]  128.91 77.99 180 bottom
PC206  22uF  [C-0805]  126.75 77.99 180 bottom
PC208  22uF  [C-0805]  130.05 81.55 0 bottom
PC209  22uF  [C-0805]  127.89 81.55 0 bottom
PC211  22uF  [C-0805]  128.52 77.34 270 top
PC212  22uF  [C-0805]  131.7 76.72 90 bottom
PC213  2.2uF  [C-0603S0]  104.79 77.99 180 top
PC214  1nF  [C-0402S0]  205.06 64.68 0 top
PC215  10nF  [C-0402S0]  193.42 25.29 90 top
PC216  100uF  [C-TAN-S7_3X4_3]  71.77 91.07 270 top
PC217  1nF  [C-0402S0]  202.56 75.58 0 top
PC218  1uF  [C-0603S0]  97.71 51.83 180 top
PC219  1uF  [C-0603S0]  73.51 76.98 180 bottom
PC220  22uF  [C-0805]  154.92 43.58 180 top
PC222  22uF  [C-1210B-H2_8]  190.5 70.63 270 bottom
PC223  100nF  [C-0402S0]  193.8 71.52 0 bottom
PC224  22uF  [C-0805]  158.22 43.58 180 top
PC225  22uF  [C-0805]  161.42 43.58 180 top
PC226  22uF  [C-0805]  155.75 60.72 0 top
PC227  22uF  [C-0805]  153.42 60.72 0 top
PC228  22uF  [C-0805]  194.82 59.71 0 top
PC229  22uF  [C-0805]  195.07 49.42 180 top
PC230  22uF  [C-0805]  191.64 49.42 180 top
PC231  22uF  [C-1210B-H2_8]  190.5 74.31 270 bottom
PC232  470uF  [C-S7_3X4_3-2]  159.46 62.39 0 top
PC233  1uF  [C-0402S0]  195.43 34.05 0 top
PC234  1uF  [C-0402S0]  198.3 28.13 270 bottom
PC235  470nF  [C-0402S0]  198.37 27.19 270 bottom
PC236  330pF  [C-0402S0]  196.44 21.37 270 top
PC237  470uF  [C-S7_3X4_3-2]  196.19 49.85 0 bottom
PC238  33pF  [C-0402S0]  196.44 22.39 270 top
PC239  1nF  [C-0402S0]  190.22 25.8 90 top
PC240  4.7nF  [C-0402S0]  190.22 27.83 90 top
PC241  100nF  [C-0402S0]  200.23 75.2 0 bottom
PC242  470uF  [C-S7_3X4_3-2]  191.01 47.64 0 bottom
PC243  22uF  [C-0805]  190.3 89.93 270 top
PC244  22uF  [C-0805]  192.66 59.71 0 top
PC246  100uF  [C-TAN-S7_3X4_3]  193.27 90.57 90 bottom
PC247  22uF  [C-0805]  93.32 45.1 180 bottom
PC248  22uF  [C-0805]  87.46 66.08 270 bottom
PC249  22uF  [C-0805]  95.78 51.98 0 bottom
PC250  22uF  [C-0805]  91.89 51.98 0 bottom
PC252  22uF  [C-0805]  96.88 47.26 270 bottom
PC255  100uF  [C-1210]  90.3 45.1 180 bottom
PC256  470uF  [C-S7_3X4_3-2]  85.6 47.01 180 bottom
PC257  22uF  [C-1210]  163.19 90.69 0 top
PC258  100nF  [C-0603S0]  162.43 90.34 180 bottom
PC259  22uF  [C-1210]  145.99 90.29 0 top
PC262  1uF  [C-0805]  149.11 90.29 0 top
PC263  22uF  [C-1210]  167.13 90.69 0 top
PC264  1uF  [C-0603S0]  86.25 32.51 90 top
PC265  22uF  [C-0805]  95.25 30.5 180 top
PC266  22uF  [C-0805]  93.85 51.98 0 bottom
PC267  10nF  [C-0402S0]  86.64 31.24 90 top
PC270  1uF  [C-0603S0]  39.32 74.33 90 top
PC271  22uF  [C-0805]  49.91 67.45 180 bottom
PC272  22uF  [C-0805]  39.37 72.66 90 top
PC273  3.3nF  [C-0402S0]  97.36 84.36 270 top
PC274  3.3nF  [C-0402S0]  95.9 92.85 0 top
PC275  3.3nF  [C-0402S0]  194.82 71.52 0 bottom
PC284  470uF  [C-S7_3X4_3-2]  191.01 60.09 180 bottom
PC292  470uF  [C-S7_3X4_3-2]  89.41 56.79 270 bottom
PC293  470uF  [C-S7_3X4_3-2]  95.6 38.12 180 bottom
PC295  1uF  [C-0603S0]  15.78 44.35 180 top
PC296  1uF  [C-0603S0]  8.97 41.44 90 top
PC297  1uF  [C-0603S0]  47.45 75.76 90 top
PC298  1uF  [C-0603S0]  18.54 82.44 180 top
PC299  1uF  [C-0603S0]  39.85 35.09 180 bottom
PC300  1uF  [C-0603S0]  52.29 30.77 270 bottom
PC301  1uF  [C-0603S0]  62.58 34.58 0 bottom
PC302  1uF  [C-0603S0]  55.34 30.77 270 bottom
PC303  1uF  [C-0603S0]  58.51 30.77 270 bottom
PC304  1uF  [C-0603S0]  45.81 29.5 270 bottom
PC305  1uF  [C-0603S0]  41.16 61.61 180 top
PC306  1uF  [C-0603S0]  43.15 30.01 270 bottom
PC307  100nF  [C-0402S0]  27.91 47.02 180 top
PC309  1uF  [C-0805]  7.18 53 0 top
PC312  1nF  [C-0402S0]  156.11 85.58 0 bottom
PC313  100nF  [C-0402S0]  157.5 87.08 270 bottom
PC316  22nF  [C-0402S0]  150.7 84.49 0 bottom
PC318  1uF  [C-0603S0]  166.75 90.26 180 bottom
PC322  1uF  [C-0603S0]  148.9 88.94 180 bottom
PC323  470uF  [C-S7_3X4_3-2]  93.98 52.34 180 top
PC324  470uF  [C-S7_3X4_3-2]  89.41 62.12 270 bottom
PC325  22uF  [C-0805]  96.88 49.29 270 bottom
PC326  22pF  [C-0402S0]  61.82 39.01 180 bottom
PC327  100uF  [C-TAN-S7_3X4_3]  71.77 85.74 270 top
PC328  1nF  [C-0402S0]  76.58 58.94 180 top
PC329  470nF  [C-0402S0]  68.07 50.56 180 bottom
PC330  3.3nF  [C-0402S0]  76.07 48.15 0 top
PC331  100nF  [C-0402S0]  78.74 40.02 180.1 top
PC332  1nF  [C-0402S0]  68.96 57.42 180 bottom
PC333  100nF  [C-0402S0]  82.04 45.74 89.6 top
PC334  6.8nF  [C-0402S0]  65.42 53.95 0 top
PC335  330pF  [C-0402S0]  65.91 46.5 180.1 top
PC336  1nF  [C-0402S0]  82.42 48.02 180 bottom
PC338  33pF  [C-0402S0]  66.42 48.91 270.2 top
PC339  4.7nF  [C-0402S0]  69.98 57.42 180 bottom
PC340  2.2uF  [C-0603S0]  82.68 51.96 0 bottom
PC347  1uF  [C-0402S0]  72.14 50.82 270 bottom
PC348  1uF  [C-0402S0]  69.22 50.56 180 bottom
PC349  22uF  [C-0805]  90.04 62.5 0 top
PJ20  0ohm  [R-0603-TESTS1]  72.11 78.88 0 top
PJ21  0ohm  [R-0603-TESTS1]  194.06 36.85 180 bottom
PJ22  0ohm  [R-0603-TESTS1]  66.29 55.52 270 bottom
PL1  2.2uH  [L-S5_49X5_18-2]  15.43 49.45 90 top
PL2  2.2uH  [L-S4_45X4_06-2AS0]  52.28 90.84 270 top
PL8  330nH 20% 20A 0.0035ohm  [L-S6_86X6_47-2A]  82.65 57.06 270 top
PL9  680nH  [L-S4_45X4_06-2AS0]  82.93 40.66 270 top
PL10  220nH  [L-S8_3X8_1-2]  111.9 89.55 270 top
PL11  330nH  [L-S6_86X6_47-2A]  80.92 88.79 270 top
PL12  330nH  [L-S6_86X6_47-2A]  195.95 79.79 270 bottom
PL13  220nH  [L-S8_3X8_1-2]  111.9 80.41 270 top
PL14  220nH  [L-S8_3X8_1-2]  201.26 59.98 0 bottom
PL15  2.2uH  [L-S5_49X5_18-2]  157.47 87.5 90 top
PL16  3.3uH 20% 5A 0.038ohm  [L-S5_49X5_18-2A]  33.61 86.01 180 top
PNTC2  100Kohm  [R-0402S0]  117.3 92.97 0 top
PNTC3  100Kohm  [R-0402S0]  111.08 74.97 270 top
PNTC4  100Kohm  [R-0402S0]  85.83 76.47 180 top
PNTC5  100Kohm  [R-0402S0]  190.22 24.78 270 top
PNTC6  100Kohm  [R-0402S0]  206.71 59.34 0 bottom
PNTC7  100Kohm  [R-0402S0]  68.07 57.42 180.8 top
PNTC8  100Kohm  [R-0402S0]  81.79 61.36 90 top
PR1  20Kohm  [R-0402S0]  8.97 40.17 90 top
PR2  20Kohm  [R-0402S0]  38.58 34.83 180 bottom
PR7  0.01ohm  [R-0805]  5.71 47.77 180 top
PR8  0.01ohm  [R-0805]  3.68 47.77 180 top
PR9  0ohm  [R-0603S0]  12.31 44.66 180 top
PR10  0.01ohm  [R-S3_1X1_6-2]  25.1 46.77 180 top
PR11  10Kohm  [R-0402S0]  42.34 67.33 270 top
PR12  4.7Kohm  [R-0402S0]  50.14 65.67 270 top
PR13  10Kohm  [R-0402S0]  54.42 76.82 180 top
PR14  2.87Kohm  [R-0402S0]  53.86 69.2 180 top
PR15  1.8Kohm  [R-0402S0]  55.46 69.58 90 top
PR16  4.12Kohm  [R-0402S0]  49.76 67.07 180 top
PR17  200Kohm  [R-0402S0]  6.05 42.83 90 top
PR18  54.9Kohm  [R-0603S0]  10.7 42.83 90 top
PR19  10Kohm  [R-0402S0]  8.57 44.62 90 top
PR20  2Mohm  [R-0402S0]  8.57 43.6 90 top
PR21  22ohm  [R-0603S0]  47.45 77.28 270 top
PR22  226Kohm  [R-0402S0]  48.21 79.06 0 top
PR23  0ohm  [R-0603S0]  47.32 89.32 90 top
PR24  49.9Kohm  [R-0402S0]  46.18 79.06 180 top
PR25  2.2  [R-0805]  52.91 90.21 0 bottom
PR26  100Kohm  [R-0402S0]  86.64 30.27 270 top
PR31  11Kohm  [R-0402S0]  28.27 83.47 180 top
PR32  182Kohm  [R-0402S0]  29.16 83.47 180 top
PR33  100Kohm  [R-0402S0]  27.13 91.28 180 top
PR34  88.7Kohm  [R-0402S0]  26.5 83.47 180 top
PR35  100Kohm  [R-0402S0]  25.61 83.47 0 top
PR36  10Kohm  [R-0402S0]  187.04 88.93 90 top
PR37  10Kohm  [R-0402S0]  183.74 88.93 90 top
PR38  0ohm  [R-0402S0]  180.82 92.22 90 top
PR42  22ohm  [R-0603S0]  24.84 81.32 270 top
PR57  470ohm  [R-0603S0]  93.62 30.65 180 top
PR73  470ohm  [R-0603S0]  40.97 81.32 270 top
PR79  100Kohm  [R-0402S0]  150.57 88.3 270 bottom
PR80  0ohm  [R-0603S0]  155.02 82.04 270 top
PR107  5.1ohm  [R-0402S0]  72.26 48.02 0 top
PR108  200ohm  [R-0402S0]  70.23 48.02 0 top
PR109  0ohm  [R-0402S0]  71.25 48.02 0 top
PR110  120ohm  [R-0402S0]  198.98 34.05 0 top
PR111  40.2ohm  [R-0402S0]  202.69 30.5 90 bottom
PR112  75ohm  [R-0402S0]  73.93 73.29 270 bottom
PR114  0ohm  [R-0603S0]  95.01 89.19 90 top
PR115  0ohm  [R-0603S0]  94.89 79.14 90 top
PR116  1.8ohm  [R-2010]  105.3 86.17 270 bottom
PR117  17.4Kohm  [R-0402S0]  111.47 88.03 90 bottom
PR118  158Kohm  [R-0402S0]  112.67 85.99 270 bottom
PR119  28.7Kohm  [R-0402S0]  112.9 88.39 180 bottom
PR120  0ohm  [R-0402S0]  110.05 88.41 0 bottom
PR121  0ohm  [R-0402S0]  113.94 88.41 0 bottom
PR122  0ohm  [R-0402S0]  95.14 86.88 270 top
PR123  1.8ohm  [R-2010]  105.3 82.36 270 bottom
PR124  17.4Kohm  [R-0402S0]  111.34 78.88 90 bottom
PR125  158Kohm  [R-0402S0]  112.67 77.69 270 bottom
PR126  28.7Kohm  [R-0402S0]  112.9 79.12 180 bottom
PR127  0ohm  [R-0402S0]  109.92 79.26 0 bottom
PR128  0ohm  [R-0402S0]  113.94 79.14 0 bottom
PR129  0ohm  [R-0402S0]  95.14 76.98 270 top
PR130  0ohm  [R-0402S0]  97.3 85.36 270 top
PR131  0ohm  [R-0402S0]  95.14 75.2 270 top
PR132  10Kohm  [R-0603S0]  83.29 81.93 90 top
PR133  10Kohm  [R-0402S0]  84.81 76.47 0 top
PR134  10Kohm  [R-0402S0]  75.41 79.64 180 top
PR135  10Kohm  [R-0402S0]  77.93 70.62 0 top
PR136  100ohm  [R-0402H016HS40]  125.14 64.35 180 bottom
PR137  100ohm  [R-0402H016HS40]  126.01 64.34 0 bottom
PR138  10ohm  [R-0603S0]  73.64 76.09 270 top
PR139  10ohm  [R-0603S0]  75.67 70.63 0 top
PR140  150Kohm  [R-0402S0]  84.3 77.84 270 top
PR141  100Kohm  [R-0402S0]  85.07 74.23 270 top
PR142  3.57Kohm  [R-0402S0]  84.3 79.52 90 top
PR143  137Kohm  [R-0402S0]  83.75 74.74 0 top
PR144  3.57Kohm  [R-0402S0]  83.96 72.38 90 top
PR145  261Kohm  [R-0402S0]  84.07 71.42 90 top
PR146  169Kohm  [R-0402S0]  82.25 70.64 0 top
PR147  150Kohm  [R-0402S0]  83.95 73.34 270 top
PR148  75Kohm  [R-0402S0]  84.07 70.19 270 top
PR149  150Kohm  [R-0402S0]  81.3 70.63 180 top
PR150  4.32Kohm  [R-0402S0]  74.03 80.94 90 top
PR151  1.1Kohm  [R-0402S0]  74.09 78.27 270 top
PR152  0ohm  [R-0402S0]  80.34 70.59 0 top
PR153  0ohm  [R-0402S0]  78.11 80.75 0 top
PR154  0ohm  [R-0603S0]  76.96 81.3 180 top
PR155  0ohm  [R-0402S0]  79.35 79.26 180 bottom
PR156  0ohm  [R-0402S0]  80.37 79.26 0 bottom
PR157  20Kohm  [R-0402S0]  190.22 22.75 90 top
PR158  75Kohm  [R-0402S0]  188.7 28.34 180 top
PR159  37.4Kohm  [R-0402S0]  190.22 23.76 270 top
PR160  2ohm  [R-1206]  205.06 68.11 0 top
PR161  18.7Kohm  [R-0402S0]  204.09 60.09 180 top
PR162  102Kohm  [R-0402S0]  204.47 58.44 270 top
PR163  28.7Kohm  [R-0402S0]  206.76 61.1 0 bottom
PR164  422Kohm  [R-0402S0]  190.22 28.84 270 top
PR165  59Kohm  [R-0402S0]  190.22 30.11 270 top
PR166  715Kohm  [R-0603S0]  190.22 33.42 270 top
PR167  0ohm  [R-0402S0]  202.69 60.72 270 top
PR168  0ohm  [R-0402S0]  202.64 58.96 270 top
PR169  169Kohm  [R-0402S0]  190.09 34.69 270 top
PR170  5.1ohm  [R-0402S0]  74.06 71.9 270 top
PR171  200ohm  [R-0402S0]  74.06 73.8 270 top
PR172  0ohm  [R-0402S0]  74.06 72.91 270 top
PR173  120ohm  [R-0402S0]  73.93 72.28 270 bottom
PR174  40.2ohm  [R-0402S0]  73.93 74.18 90 bottom
PR175  75ohm  [R-0402S0]  71.25 45.48 0 top
PR176  150Kohm  [R-0402S0]  190.22 31.13 90 top
PR177  75Kohm  [R-0402S0]  190.22 32.15 90 top
PR178  150Kohm  [R-0402S0]  190.09 35.58 90 top
PR179  5.1ohm  [R-0402S0]  197.97 34.05 180 top
PR180  200ohm  [R-0402S0]  200.28 30.5 270 bottom
PR181  0ohm  [R-0402S0]  203.58 75.58 180 top
PR182  0ohm  [R-0402S0]  200.28 31.51 270 bottom
PR183  10Kohm  [R-0402S0]  197.1 23.26 90 top
PR184  2.67Kohm  [R-0402S0]  198.37 26.31 90 bottom
PR185  10Kohm  [R-0603S0]  192.15 23.77 0 top
PR186  0ohm  [R-0402S0]  193.4 34.05 180 top
PR187  0ohm  [R-0402S0]  194.15 23.66 180 top
PR188  0ohm  [R-0402S0]  195.17 23.66 0 top
PR189  10Kohm  [R-0402S0]  190.22 26.81 90 top
PR190  10Kohm  [R-0402S0]  197.54 24.58 270 top
PR191  10Kohm  [R-0402S0]  180.82 91.2 270 top
PR192  100ohm  [R-0402S0]  194.15 21.34 180 top
PR193  100ohm  [R-0402S0]  195.17 21.34 0 top
PR194  10ohm  [R-0603S0]  201.04 27.75 270 bottom
PR195  10ohm  [R-0603S0]  196.7 34.31 180 top
PR196  120ohm  [R-0402S0]  72.26 45.48 0 top
PR197  40.2ohm  [R-0402S0]  70.23 45.48 180 top
PR198  0ohm  [R-0402S0]  201.53 75.6 180 top
PR199  0ohm  [R-0603S0]  198.25 75.07 270 bottom
PR200  100Kohm  [R-0402S0]  194.41 34.05 0 top
PR201  75ohm  [R-0402S0]  202.69 31.51 270 bottom
PR202  56Kohm  [R-0402S0]  79.14 70.6 180 top
PR203  10Kohm  [R-0402S0]  197.97 34.81 0 bottom
PR204  10ohm  [R-0402S0]  152.91 81.18 0 top
PR205  2.2  [R-0805]  152.66 87.34 180 bottom
PR206  22.6Kohm  [R-0402S0]  151.97 81.18 180 top
PR207  10Kohm  [R-0402S0]  150.61 81.91 90 top
PR209  10Kohm  [R-0402S0]  76.48 76.72 0 bottom
PR210  10Kohm  [R-0402S0]  200.89 29.23 270 bottom
PR214  20Kohm  [R-0603S0]  17.28 41.05 180 top
PR215  3.6Kohm  [R-0603S0]  15.75 41.05 0 top
PR216  0ohm  [R-0603S0]  17.28 44.35 0 top
PR217  3Kohm  [R-0603S0]  18.8 44.35 180 top
PR218  0ohm  [R-0603S0]  6.56 40.95 0 top
PR219  0ohm  [R-0603S0]  41.24 35.09 180 bottom
PR221  0ohm  [R-0603S0]  50.16 75.76 270 top
PR222  20Kohm  [R-0402S0]  47.74 74.36 90 top
PR223  20Kohm  [R-0402S0]  16.89 82.69 180 top
PR224  0ohm  [R-0603S0]  18.54 85.49 0 top
PR226  20Kohm  [R-0402S0]  52.55 29.24 270 bottom
PR227  0ohm  [R-0603S0]  52.29 32.29 270 bottom
PR228  20Kohm  [R-0402S0]  63.85 34.7 0 bottom
PR229  0ohm  [R-0603S0]  61.18 34.58 0 bottom
PR231  20Kohm  [R-0402S0]  55.47 29.5 270 bottom
PR232  0ohm  [R-0603S0]  55.34 32.16 270 bottom
PR233  20Kohm  [R-0402S0]  58.39 29.5 270 bottom
PR234  0ohm  [R-0603S0]  58.51 32.16 270 bottom
PR235  4.7Kohm  [R-0402S0]  39.77 61.86 180 top
PR236  0ohm  [R-0603S0]  38.37 61.48 180 top
PR237  20Kohm  [R-0402S0]  43.27 28.61 270 bottom
PR238  0ohm  [R-0603S0]  43.15 31.53 270 bottom
PR239  20Kohm  [R-0402S0]  45.94 28.23 270 bottom
PR241  0ohm  [R-0603S0]  45.81 30.89 270 bottom
PR242  100Kohm  [R-0402S0]  50.41 79.06 0 top
PR243  0.01ohm  [R-S3_1X1_6-2]  39.5 90.19 90 top
PR244  100Kohm  [R-0402S0]  6.05 43.85 270 top
PR245  0.01ohm  [R-S3_1X1_6-2]  22.56 46.77 180 top
PR246  330  [R-0805]  24.38 51.96 0 top
PR247  2.2  [R-0805]  10.87 50.18 180 bottom
PR248  10ohm  [R-0402S0]  12.91 42.83 90 top
PR249  10K  [R-0402S0]  13.9 49.74 90 bottom
PR250  0.01ohm  [R-0805]  144.78 85.11 180 top
PR251  0.01ohm  [R-0805]  22.12 91.2 270 top
PR252  10Kohm  [R-0402S0]  40.85 80.05 270 top
PR254  0.01ohm  [R-S3_1X1_6-2]  172.69 92.41 270 top
PR259  330  [R-0805]  165.1 90.36 180 bottom
PR260  2Mohm  [R-0402S0]  150.61 80.9 90 top
PR261  10K  [R-0402S0]  155.69 87.04 90 bottom
PR263  0.01ohm  [R-0805]  146.81 85.11 180 top
PR265  36Kohm  [R-0402S0]  147.63 88.96 180 bottom
PR266  0.01ohm  [R-S3_1X1_6-2]  172.69 89.74 270 top
PR267  0ohm  [R-0603S0]  29.29 91.6 0 top
PR268  499Kohm  [R-0402S0]  69.09 57.42 179.8 top
PR269  75Kohm  [R-0402S0]  73.03 57.42 180 bottom
PR271  9.31Kohm  [R-0402S0]  73.79 57.42 179.9 top
PR272  100ohm  [R-0402S0]  65.79 49.67 180.3 bottom
PR273  0ohm  [R-0603S0]  81.79 44.47 269.7 top
PR274  20Kohm  [R-0402S0]  66.93 57.42 180 bottom
PR275  150Kohm  [R-0402S0]  70.99 57.42 180 bottom
PR276  10Kohm  [R-0402S0]  66.93 46.5 0 top
PR277  10Kohm  [R-0402S0]  74.04 51.83 90 top
PR278  100ohm  [R-0402S0]  65.02 52.21 359.7 bottom
PR279  10Kohm  [R-0603S0]  65.66 57.29 180 top
PR280  0ohm  [R-0402S0]  74.04 53.74 270 top
PR281  0ohm  [R-0402S0]  74.04 55.77 90 top
PR282  64.9Kohm  [R-0402S0]  67.06 57.42 180.6 top
PR284  100Kohm  [R-0402S0]  74.04 52.72 270 top
PR285  150Kohm  [R-0402S0]  72.01 57.42 180 bottom
PR286  0ohm  [R-0603S0]  64.39 49.42 270 top
PR287  75Kohm  [R-0402S0]  82.55 58.94 270 bottom
PR289  0ohm  [R-0402S0]  74.04 54.75 270 top
PR290  0ohm  [R-0402S0]  65.79 51.45 0.2 top
PR291  28.7Kohm  [R-0402S0]  83.44 61.36 90 top
PR292  2.2Mohm  [R-0402S0]  72.77 57.42 180 top
PR293  0ohm  [R-0402S0]  82.55 56.02 90 bottom
PR294  19.6Kohm  [R-0402S0]  82.55 58.06 270 bottom
PR295  10ohm  [R-0603S0]  73.28 52.85 270 bottom
PR296  150Kohm  [R-0402S0]  74.04 57.42 180 bottom
PR297  10ohm  [R-0603S0]  68.83 47.9 180 bottom
PR298  2.67Kohm  [R-0402S0]  67.94 48.02 0 top
PR299  0ohm  [R-0402S0]  83.82 58.56 180.3 bottom
PR300  6.8Kohm  [R-0402S0]  67.94 57.42 180 bottom
PR301  10Kohm  [R-0402S0]  66.42 47.9 269.5 top
PR302  10Kohm  [R-0402S0]  69.22 48.02 0 top
PR303  93.1Kohm  [R-0402S0]  70.74 57.42 180 top
PR304  2ohm  [R-1206]  76.58 55.77 180 top
PR305  2.2Mohm  [R-0402S0]  71.75 57.42 180 top
PU1  TPS563219ADDFR  [SOT-23-8A]  9.59 48.43 90 top
PU2  TPS56428DDAR  [SO-8GSHS0]  48.46 84.14 270 top
PU5  TPS74801DRCR  [TQFN-3X3-10GSH]  54.25 73.01 90 top
PU6  TPS74801DRCR  [TQFN-3X3-10GSH]  46.28 66 180 top
PU11  TPS51200  [TQFN-3X3-10FSHS1]  184.76 92.09 0 top
PU14  TPS54218RTER  [TQFN-3X3-16TSHS0]  28.1 87.39 270 top
PU17  TPS51631ARSMR  [S-UQFN-4X4-32BSH]  79.05 75.68 0 top
PU18  CSD95372AQ5M  [TQFN-6X5-22SHS1]  100.18 90.06 0 top
PU19  CSD95372AQ5M  [TQFN-6X5-22SHS1]  100.18 80.03 0 top
PU20  TPS563219ADDFR  [SOT-23-8A]  151.37 85.72 90 top
PU21  TPS53623RSMR  [S-UQFN-4X4-32BSH]  195.63 28.54 180 top
PU22  CSD95373AQ5M  [TQFN-6X5-22SHS1]  199.2 69.74 270 bottom
PU24  NCP45540IMNTWG-H  [TLGA-3X3-12SH]  90.32 32.51 180 top
PU25  NCP45524IMNTWG-H  [TQFN-2X2-8FSHS0]  40.97 77.28 270 top
PU26  CSD95373AQ5M  [TQFN-6X5-22SHS1]  80.52 49.93 90 top
PU27  TPS53623RSMR  [S-UQFN-4X4-32BSH]  69.6 52.85 90 top
Q1  PMGD280UN  [SOT-363S0]  78.88 39 180 bottom
Q2  MMBT3904LT1G  [SOT-23BH1_11]  34.42 23.77 0 bottom
Q3  MMBT3904LT1G  [SOT-23BH1_11]  38.48 23.77 270 bottom
Q4  PMGD280UN  [SOT-363S0]  58.27 53.36 0 top
Q5  PMGD280UN  [SOT-363S0]  54.59 53.36 180 top
Q6  MMBT3904LT1G  [SOT-23BH1_11]  53.98 22.17 90 bottom
R1  1Kohm  [C-0402B-U58O293T00]  116.3 54.18 0 bottom
R2  5.11Kohm  [R-0402S0]  106.82 68.34 180 top
R3  5.11Kohm  [R-0402S0]  104.02 65.53 270 top
R4  10Kohm  [R-0402S0]  82.26 66.45 270 bottom
R5  2.2Kohm  [R-0402S0]  69.56 64.55 270 bottom
R6  2.2Kohm  [R-0402S0]  82.01 64.3 90 bottom
R7  10Kohm  [R-0402S0]  103.99 60.34 90 top
R8  10Kohm  [R-0402S0]  103.99 61.48 90 top
R9  10Kohm  [R-0402S0]  115.59 59.98 0 bottom
R10  10Kohm  [R-0402S0]  109.75 60.95 0 bottom
R11  10Kohm  [R-0402S0]  115.34 58.29 90 bottom
R12  33ohm  [R-0402S0]  84.66 62.39 270 top
R13  33ohm  [R-0402S0]  82.26 65.31 90 bottom
R14  5.11Kohm  [R-0402S0]  84.3 26.58 270 bottom
R15  5.11Kohm  [R-0402S0]  84.3 27.59 270 bottom
R16  10Kohm  [R-0402S0]  103.99 62.63 90 bottom
R17  10Kohm  [R-0402S0]  114.82 69.87 0 top
R18  4.7Kohm  [R-0402S0]  93.55 28.1 270 bottom
R19  33ohm  [R-0402S0]  69.69 65.9 270 top
R20  33ohm  [R-0402S0]  69.69 64.88 270 top
R21  33ohm  [R-0402S0]  69.69 63.86 270 top
R29  7.5Kohm  [R-0402S0]  144.62 12.86 180 top
R30  7.5Kohm  [C-0402B-U58O293T00]  126.96 43.56 90 bottom
R31  220ohm  [R-0402S0]  147.54 13.37 0 top
R32  22.6ohm  [C-0402B-U58O293T00]  119.26 31.57 270 bottom
R33  10Kohm  [R-0402S0]  134.08 3.72 0 top
R34  10Kohm  [R-0402S0]  141.7 13.37 0 top
R35  10Kohm  [R-0402S0]  143.22 13.37 0 top
R36  10Kohm  [R-0402S0]  137.13 3.72 0 top
R37  10Kohm  [C-0402B-U58O293T00]  128.23 44.32 90 bottom
R38  10Kohm  [C-0402B-U58O293T00]  130.45 44.78 0 bottom
R39  33ohm  [R-0402S0]  170.94 6.11 90 bottom
R40  33ohm  [R-0402S0]  182.37 5.35 270 bottom
R41  0ohm  [R-0402S0]  138.65 3.72 0 bottom
R42  0ohm  [R-0402S0]  129.51 3.72 0 bottom
R43  0ohm  [R-0402S0]  132.56 8.03 180 top
R44  0ohm  [R-0402S0]  137.13 8.03 0 bottom
R45  0ohm  [R-0402S0]  47.75 27.7 90 top
R46  0ohm  [R-0402S0]  47.75 26.69 90 top
R47  0ohm  [R-0402S0]  106.39 16.16 0 top
R48  0ohm  [R-0402S0]  126.46 3.72 0 bottom
R49  0ohm  [R-0402S0]  127.98 13.37 0 bottom
R50  7.5Kohm  [C-0402B-U58O293T00]  117.83 36.56 180 bottom
R51  51ohm  [C-0402B-U58O293T00]  117.82 66.06 0 bottom
R52  33ohm  [R-0402S0]  131.03 13.37 0 bottom
R53  33ohm  [R-0402S0]  70.25 28.72 0 top
R54  33ohm  [R-0402S0]  118.46 18.07 0 bottom
R55  33ohm  [R-0402S0]  115.44 18.07 180 top
R56  33ohm  [R-0402S0]  116.93 18.07 180 top
R57  33ohm  [R-0402S0]  115.41 18.07 0 bottom
R58  33ohm  [R-0402S0]  116.93 18.07 0 bottom
R59  4.7Kohm  [R-0402S0]  131.03 17.18 180 bottom
R60  4.7Kohm  [R-0402S0]  127.76 21.99 180 bottom
R61  10Mohm  [R-0603S0]  122.94 22.62 270 top
R62  1Kohm  [R-0402S0]  139.92 17.18 0 top
R63  1Kohm  [R-0402S0]  132.56 3.72 0 top
R64  10Kohm  [R-0402S0]  134.08 17.18 180 bottom
R65  4.7Kohm  [C-0402B-U58O293T00]  125.65 40.92 0 bottom
R66  240ohm  [R-0402S0]  118.08 62.96 90 bottom
R67  4.7Kohm  [C-0402B-U58O293T00]  128.18 42.72 90 bottom
R68  1Kohm  [R-0402S0]  126.46 8.03 0 top
R69  1Kohm  [R-0402S0]  145.16 10.68 270 bottom
R70  10Kohm  [C-0402B-U58O293T00]  126.84 41.73 0 bottom
R71  10Kohm  [C-0402B-U58O293T00]  124.61 28.44 90 bottom
R72  49.9ohm  [C-0402B-U58O293T00]  119.32 56.61 180 bottom
R73  10Kohm  [C-0402B-U58O293T00]  128.62 40.06 0 bottom
R74  10Kohm  [R-0402S0]  127.98 13.37 0 top
R75  10Kohm  [C-0402B-U58O293T00]  129.76 40.04 0 bottom
R76  5.11Kohm  [R-0402S0]  127.98 17.18 0 top
R77  10Kohm  [R-0402S0]  125.74 33.52 90 bottom
R78  1Mohm  [R-0402S0]  120.87 27.08 0 bottom
R79  10Kohm  [C-0402B-U58O293T00]  128.7 35.71 0 bottom
R80  10Kohm  [C-0402B-U58O293T00]  125.63 42.13 90 bottom
R81  10Kohm  [C-0402B-U58O293T00]  124.61 30.09 90 bottom
R82  5.11Kohm  [C-0402B-U58O293T00]  124.83 32.41 90 bottom
R83  3.32Kohm  [C-0402B-U58O293T00]  124.61 29.26 90 bottom
R84  10Kohm  [R-0402S0]  131.03 3.72 0 top
R85  2.2Kohm  [R-0402S0]  118 64.66 90 bottom
R86  0ohm  [R-0402S0]  23.11 19.45 90 bottom
R87  1Kohm  [R-0402S0]  126.46 17.18 0 top
R88  0ohm  [R-0402S0]  24.89 19.45 90 bottom
R89  10Kohm  [C-0402B-U58O293T00]  127.61 36.04 0 bottom
R90  10Kohm  [C-0402B-U58O293T00]  122.53 56.08 270 bottom
R91  10Kohm  [C-0402B-U58O293T00]  127.55 39.67 180 bottom
R92  0ohm  [R-0402S0]  26.8 19.45 270 bottom
R93  10Kohm  [R-0402S0]  104.02 64.51 270 top
R94  0ohm  [R-0402S0]  28.57 20.21 90 bottom
R95  5.11Kohm  [R-0402S0]  113.94 69.87 180 top
R96  1Kohm  [C-0402B-U58O293T00]  118 63.8 270 bottom
R97  10Kohm  [R-0402S0]  118.46 18.07 0 top
R98  10Kohm  [R-0402S0]  127.98 8.03 180 bottom
R99  4.7Kohm  [R-0402S0]  127.98 3.72 0 top
R100  10Kohm  [R-0402S0]  127.98 8.03 180 top
R101  10Kohm  [R-0402S0]  70.25 26.94 0 top
R102  33ohm  [R-0402S0]  183.77 5.86 270 top
R103  0ohm  [R-0402S0]  43.05 19.96 270 bottom
R104  10ohm  [R-0402S0]  32.35 45.75 90 top
R105  0ohm  [R-0402S0]  119.18 71.75 90 top
R106  0ohm  [C-0402B-U58O293T00]  121.85 63.34 270 bottom
R107  0ohm  [C-0402B-U58O293T00]  120.54 64.61 180 bottom
R108  220ohm  [C-0402B-U58O293T00]  123.07 62.45 270 bottom
R109  10Kohm  [R-0402S0]  123.27 54.78 90 bottom
R110  75ohm  [R-0402S0]  27.24 66.82 270 top
R111  10Kohm  [R-0402S0]  84.58 30.24 180 bottom
R112  10Kohm  [R-0402S0]  83.26 33.56 90 bottom
R113  240ohm  [R-0402S0]  121.2 54.68 90 bottom
R114  10Kohm  [R-0402S0]  104.02 63.49 270 top
R115  1Kohm  [R-0402S0]  111.6 69.88 180 top
R116  240ohm  [R-0402S0]  143.02 80.41 90 top
R117  240ohm  [R-0402S0]  140.56 81.17 180 top
R118  4.7Kohm  [R-0402S0]  143.27 90.57 180 top
R119  120ohm  [C-0402B-U58O293T00]  121.83 64.16 270 bottom
R120  1Kohm  [R-0402S0]  142.26 90.57 0 top
R121  1Kohm  [R-0402S0]  141.24 90.57 0 top
R122  49.9ohm  [C-0402B-U58O293T00]  123.11 63.7 0 bottom
R123  5.11Kohm  [R-0402S0]  109.57 69.88 180 top
R124  5.11Kohm  [R-0402S0]  118.76 69.87 180 top
R125  10ohm  [R-0402S0]  143.02 81.55 90 top
R126  20ohm  [R-0402S0]  142.26 90.57 180 bottom
R127  10ohm  [R-0402S0]  141.58 81.17 180 top
R128  20ohm  [R-0402S0]  141.24 90.57 180 bottom
R129  20Kohm  [R-0402S0]  197.61 13.1 180 top
R130  20Kohm  [R-0402S0]  198.63 3.95 180 bottom
R131  1Kohm  [R-0402S0]  199.64 3.95 180 bottom
R132  1Kohm  [R-0402S0]  202.56 3.95 180 bottom
R133  1Kohm  [R-0603S0]  197.49 38.24 0 bottom
R134  1Mohm  [R-0402S0]  112.42 24.63 90 top
R135  10Kohm  [C-0402B-U58O293T00]  117.34 41.75 90 bottom
R136  22ohm  [R-0402S0]  112.14 28.46 270 bottom
R137  10Kohm  [C-0402B-U58O293T00]  115.74 41.75 180 bottom
R138  10Kohm  [R-0402S0]  116.1 27.55 90 bottom
R139  22ohm  [C-0402B-U58O293T00]  116.63 31.4 0 bottom
R140  10Kohm  [C-0402B-U58O293T00]  119.4 27.92 0 bottom
R141  10Kohm  [C-0402B-U58O293T00]  113.33 41.35 90 bottom
